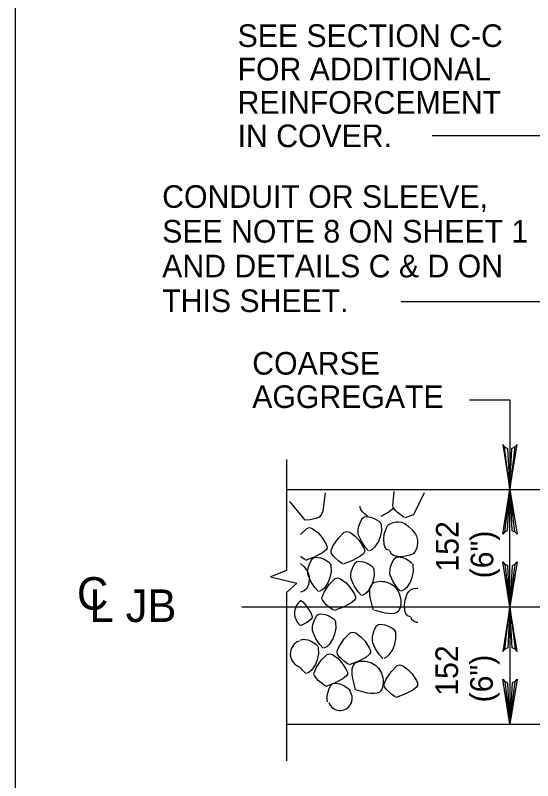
# Model space of a CAD drawing. Extents: x 638455 to 640199, y 298558 to 299152.
# Drawn here: x 639333.6 to 639410.6, y 298979.8 to 299093.5 of the extents above; entities that cross this region are included whole.
import ezdxf

# ---------------------------------------------------------------- set-up
doc = ezdxf.new("R2010")
doc.units = 0
for name, color, linetype in [('1', 7, 'Continuous'), ('2', 7, 'Continuous'), ('3', 7, 'Continuous')]:
    doc.layers.add(name, color=color, linetype=linetype)

msp = doc.modelspace()

# ---------------------------------------------------------------- linework, layer by layer
at = {"layer": '1'}
msp.add_lwpolyline([(640119.61, 298573.25), (640119.61, 299137.25), (639333.61, 299137.25), (639333.61, 298573.25), (640119.61, 298573.25), (640119.61, 298599.61), (639919.61, 298599.61), (639919.61, 298664.29), (640119.61, 298664.29), (640119.61, 298693.25), (639919.61, 298693.25), (639919.61, 298573.25), (639998.42, 298573.25), (639998.42, 298599.61), (639998.42, 298573.25), (640075.42, 298573.25), (640075.42, 298599.61), (640075.42, 298587.29), (640119.61, 298587.29)], dxfattribs=at)
for centre, radius, start, end in [((639377.44, 299004.64), 2.3, 128.3504, 231.6496), ((639376.57, 298998.59), 2.06, 110.8458, 251.6988), ((639381.92, 298992), 1.8, 199.608, 34.7802)]:
    msp.add_arc(centre, radius, start, end, dxfattribs=at)
at = {"layer": '2'}
for p, q in [((639395.61, 299075.6), (639424.14, 299075.6)), ((639391.01, 299050.97), (639421.85, 299050.97)), ((639401.16, 299036.35), (639407.17, 299036.35)), ((639407.17, 299036.35), (639407.17, 299023.03)), ((639373.95, 299027.49), (639373.95, 299010.98)), ((639373.94, 299023.03), (639513.29, 299023.03)), ((639407.17, 299005.61), (639407.17, 299023.03)), ((639373.95, 299007.72), (639373.95, 298982.72)), ((639367.29, 299005.61), (639411.68, 299005.61)), ((639407.17, 299005.61), (639407.17, 298988.18)), ((639373.95, 298988.18), (639513.29, 298988.18))]:
    msp.add_line(p, q, dxfattribs=at)
for points in [[(639406.37, 299029.36), (639406.83, 299029.13), (639407.17, 299023.03), (639406.37, 299029.36), (639406.1, 299029.69), (639407.17, 299023.03), (639407.47, 299029.12), (639407.92, 299029.34), (639407.17, 299023.03), (639408.23, 299029.69), (639407.92, 299029.34)], [(639379.71, 299022.54), (639379.33, 299019.82)], [(639389.76, 299020.61), (639389.94, 299022.71)], [(639394.41, 299022.54), (639392.83, 299019.27)], [(639406.37, 299016.7), (639406.83, 299016.94), (639407.17, 299023.03), (639406.37, 299016.7), (639406.1, 299016.38), (639407.17, 299023.03), (639407.47, 299016.94), (639407.92, 299016.72), (639407.17, 299023.03), (639408.23, 299016.38), (639407.92, 299016.72)], [(639376.71, 299018.49), (639374.46, 299021.25)], [(639384.9, 299020.36), (639384.91, 299020.57)], [(639384.96, 299020.14), (639384.9, 299020.36)], [(639385.25, 299019.71), (639384.96, 299020.14)], [(639389.72, 299020.1), (639389.18, 299019.66)], [(639389.87, 299020.35), (639389.72, 299020.1)], [(639389.82, 299020.39), (639389.76, 299020.61)], [(639390.11, 299019.96), (639389.82, 299020.39)], [(639390.39, 299019.67), (639390.11, 299019.96)], [(639378.36, 299018.72), (639377.44, 299018.5)], [(639378.78, 299018.93), (639378.36, 299018.72)], [(639379.1, 299019.25), (639378.78, 299018.93)], [(639379.33, 299019.82), (639379.1, 299019.25)], [(639384.93, 299018.22), (639385.23, 299018.77)], [(639385.23, 299018.77), (639385.48, 299018.97)], [(639385.54, 299019.42), (639385.25, 299019.71)], [(639385.48, 299018.97), (639385.79, 299019.03)], [(639385.98, 299019.06), (639385.54, 299019.42)], [(639385.79, 299019.03), (639386.46, 299018.93)], [(639386.46, 299018.93), (639386.99, 299018.73)], [(639386.99, 299018.73), (639387.67, 299018.31)], [(639389.18, 299019.66), (639387.97, 299019.02)], [(639390.84, 299019.3), (639390.39, 299019.67)], [(639391.46, 299018.85), (639390.84, 299019.3)], [(639392.83, 299019.27), (639391.54, 299018.79)], [(639377.44, 299018.5), (639376.71, 299018.49)], [(639384.6, 299017.11), (639384.7, 299017.57)], [(639384.7, 299017.57), (639384.93, 299018.22)], [(639387.67, 299018.31), (639387.9, 299018.07)], [(639387.9, 299018.07), (639388.02, 299017.84)], [(639388.02, 299017.84), (639388.05, 299016.86)], [(639388.8, 299017.35), (639389.03, 299017.7)], [(639389.03, 299017.7), (639389.3, 299017.93)], [(639389.3, 299017.93), (639389.8, 299018.13)], [(639389.8, 299018.13), (639390.25, 299018.21)], [(639390.25, 299018.21), (639390.6, 299018.22)], [(639390.6, 299018.22), (639391.1, 299018.15)], [(639391.1, 299018.15), (639391.55, 299017.96)], [(639391.55, 299017.96), (639392, 299017.63)], [(639392, 299017.63), (639392.61, 299017.05)], [(639376.08, 299016.37), (639376.96, 299017.25)], [(639376.96, 299017.25), (639377.35, 299017.36)], [(639377.35, 299017.36), (639377.78, 299017.23)], [(639377.78, 299017.23), (639378.58, 299016.63)], [(639378.58, 299016.63), (639379.16, 299016)], [(639381.66, 299015.81), (639382.53, 299016.69)], [(639382.53, 299016.69), (639382.93, 299016.8)], [(639382.93, 299016.8), (639383.35, 299016.66)], [(639383.35, 299016.66), (639384.16, 299016.07)], [(639384.6, 299016.53), (639384.6, 299017.11)], [(639384.67, 299016.24), (639384.6, 299016.53)], [(639388.05, 299016.86), (639387.86, 299015.97)], [(639388.49, 299016.41), (639388.8, 299017.35)], [(639392.61, 299017.05), (639393.13, 299016.38)], [(639376.04, 299016.32), (639376.08, 299016.37)], [(639379.16, 299016), (639379.8, 299015.02)], [(639380.87, 299014.68), (639381.66, 299015.81)], [(639384.16, 299016.07), (639384.73, 299015.44)], [(639385.08, 299015.33), (639384.67, 299016.24)], [(639384.73, 299015.44), (639385.38, 299014.46)], [(639385.66, 299014.45), (639385.08, 299015.33)], [(639387.61, 299015.3), (639387.04, 299014.44)], [(639387.86, 299015.97), (639387.61, 299015.3)], [(639388.41, 299015.71), (639388.49, 299016.41)], [(639388.48, 299014.84), (639388.41, 299015.71)], [(639393.13, 299016.38), (639393.27, 299016.1)], [(639393.27, 299016.1), (639393.4, 299015.51)], [(639393.4, 299015.51), (639393.41, 299015.05)], [(639379.8, 299015.02), (639379.96, 299014.61)], [(639379.97, 299014.3), (639379.82, 299014.05)], [(639379.96, 299014.61), (639379.97, 299014.3)], [(639380.59, 299013.96), (639380.87, 299014.68)], [(639385.38, 299014.46), (639385.53, 299014.05)], [(639386.16, 299013.93), (639385.66, 299014.45)], [(639387.04, 299014.44), (639386.68, 299014.13)], [(639388.62, 299014.43), (639388.48, 299014.84)], [(639388.87, 299014.09), (639388.62, 299014.43)], [(639393.3, 299014.37), (639393.07, 299013.8)], [(639393.41, 299015.05), (639393.3, 299014.37)], [(639376.09, 299013.01), (639376.04, 299013.04)], [(639379.29, 299013.61), (639378.08, 299012.98)], [(639379.82, 299014.05), (639379.29, 299013.61)], [(639380.58, 299013.75), (639380.59, 299013.96)], [(639380.64, 299013.53), (639380.58, 299013.75)], [(639380.93, 299013.1), (639380.64, 299013.53)], [(639381.21, 299012.81), (639380.93, 299013.1)], [(639384.86, 299013.05), (639383.65, 299012.41)], [(639385.4, 299013.49), (639384.86, 299013.05)], [(639385.54, 299013.74), (639385.4, 299013.49)], [(639385.53, 299014.05), (639385.54, 299013.74)], [(639386.68, 299014.13), (639386.28, 299013.93)], [(639389.3, 299013.94), (639388.87, 299014.09)], [(639389.52, 299013.49), (639389.38, 299013.88)], [(639389.86, 299013.23), (639389.52, 299013.49)], [(639390.18, 299013.11), (639389.86, 299013.23)], [(639390.68, 299013.03), (639390.18, 299013.11)], [(639391.41, 299013.05), (639390.68, 299013.03)], [(639392.34, 299013.26), (639391.41, 299013.05)], [(639392.76, 299013.48), (639392.34, 299013.26)], [(639393.07, 299013.8), (639392.76, 299013.48)], [(639376.04, 299012.03), (639376.5, 299011.59)], [(639376.7, 299012.56), (639376.09, 299013.01)], [(639378.08, 299012.98), (639376.79, 299012.5)], [(639377.23, 299011.52), (639377.46, 299012.17)], [(639377.46, 299012.17), (639377.76, 299012.72)], [(639377.76, 299012.72), (639378.01, 299012.92)], [(639378.01, 299012.92), (639378.32, 299012.98)], [(639378.32, 299012.98), (639378.99, 299012.88)], [(639378.99, 299012.88), (639379.52, 299012.68)], [(639379.52, 299012.68), (639380.2, 299012.26)], [(639380.2, 299012.26), (639380.43, 299012.02)], [(639380.43, 299012.02), (639380.55, 299011.79)], [(639381.66, 299012.45), (639381.21, 299012.81)], [(639382.28, 299011.99), (639381.66, 299012.45)], [(639383.65, 299012.41), (639382.36, 299011.93)], [(639383.86, 299011.59), (639384.16, 299012.14)], [(639384.16, 299012.14), (639384.41, 299012.34)], [(639384.41, 299012.34), (639384.72, 299012.4)], [(639384.72, 299012.4), (639385.39, 299012.3)], [(639385.39, 299012.3), (639385.92, 299012.1)], [(639385.92, 299012.1), (639386.6, 299011.68)], [(639389.43, 299011.54), (639389.67, 299012.19)], [(639389.67, 299012.19), (639389.97, 299012.74)], [(639389.97, 299012.74), (639390.21, 299012.94)], [(639390.21, 299012.94), (639390.52, 299013)], [(639390.52, 299013), (639391.19, 299012.9)], [(639391.19, 299012.9), (639391.72, 299012.7)], [(639391.72, 299012.7), (639392.4, 299012.28)], [(639392.4, 299012.28), (639392.63, 299012.04)], [(639392.63, 299012.04), (639392.75, 299011.81)], [(639407.96, 299011.94), (639407.5, 299011.7), (639407.17, 299005.61), (639407.96, 299011.94), (639408.24, 299012.26), (639407.17, 299005.61), (639406.87, 299011.69), (639406.41, 299011.92), (639407.17, 299005.61), (639406.11, 299012.26), (639406.41, 299011.92)], [(639373.95, 299010.98), (639371.57, 299010.07), (639375.5, 299009.1), (639373.95, 299007.72)], [(639376.5, 299011.59), (639377.01, 299010.93)], [(639377.01, 299010.93), (639377.16, 299010.64)], [(639377.13, 299011.06), (639377.23, 299011.52)], [(639377.13, 299010.49), (639377.13, 299011.06)], [(639380.58, 299010.81), (639380.39, 299009.92)], [(639380.55, 299011.79), (639380.58, 299010.81)], [(639383.53, 299010.49), (639383.63, 299010.94)], [(639383.63, 299010.94), (639383.86, 299011.59)], [(639386.6, 299011.68), (639386.83, 299011.45)], [(639386.83, 299011.45), (639386.95, 299011.21)], [(639386.95, 299011.21), (639386.98, 299010.24)], [(639389.33, 299010.51), (639389.34, 299011.08)], [(639389.34, 299011.08), (639389.43, 299011.54)], [(639392.78, 299010.83), (639392.59, 299009.94)], [(639392.75, 299011.81), (639392.78, 299010.83)], [(639377.2, 299010.19), (639377.13, 299010.49)], [(639377.16, 299010.64), (639377.29, 299010.06)], [(639377.61, 299009.28), (639377.2, 299010.19)], [(639377.29, 299010.06), (639377.3, 299009.59)], [(639380.39, 299009.92), (639380.14, 299009.25)], [(639380.3, 299008.9), (639381.18, 299009.78)], [(639381.18, 299009.78), (639381.57, 299009.89)], [(639381.57, 299009.89), (639381.99, 299009.75)], [(639381.99, 299009.75), (639382.8, 299009.16)], [(639383.53, 299009.91), (639383.53, 299010.49)], [(639383.6, 299009.61), (639383.53, 299009.91)], [(639384.01, 299008.7), (639383.6, 299009.61)], [(639386.98, 299010.24), (639386.79, 299009.34)], [(639389.4, 299010.21), (639389.33, 299010.51)], [(639389.81, 299009.3), (639389.4, 299010.21)], [(639392.59, 299009.94), (639392.34, 299009.27)], [(639377.19, 299008.91), (639376.96, 299008.34)], [(639377.3, 299009.59), (639377.19, 299008.91)], [(639378.19, 299008.4), (639377.61, 299009.28)], [(639379.52, 299007.76), (639380.3, 299008.9)], [(639380.14, 299009.25), (639379.58, 299008.39)], [(639382.8, 299009.16), (639383.38, 299008.53)], [(639383.38, 299008.53), (639384.02, 299007.55)], [(639384.59, 299007.83), (639384.01, 299008.7)], [(639386.54, 299008.68), (639385.97, 299007.82)], [(639386.79, 299009.34), (639386.54, 299008.68)], [(639390.39, 299008.42), (639389.81, 299009.3)], [(639392.34, 299009.27), (639391.78, 299008.42)], [(639376.22, 299007.81), (639376.04, 299007.77)], [(639376.64, 299008.03), (639376.22, 299007.81)], [(639376.96, 299008.34), (639376.64, 299008.03)], [(639378.69, 299007.88), (639378.19, 299008.4)], [(639379.22, 299008.08), (639378.81, 299007.88)], [(639379.58, 299008.39), (639379.22, 299008.08)], [(639379.23, 299007.05), (639379.52, 299007.76)], [(639384.02, 299007.55), (639384.18, 299007.13)], [(639385.09, 299007.3), (639384.59, 299007.83)], [(639385.62, 299007.51), (639385.2, 299007.3)], [(639385.97, 299007.82), (639385.62, 299007.51)], [(639390.9, 299007.9), (639390.39, 299008.42)], [(639391.42, 299008.1), (639391.01, 299007.9)], [(639391.78, 299008.42), (639391.42, 299008.1)], [(639391.57, 299006.58), (639391.88, 299007.51)], [(639391.88, 299007.51), (639392.11, 299007.87)], [(639392.11, 299007.87), (639392.38, 299008.1)], [(639392.38, 299008.1), (639392.89, 299008.3)], [(639392.89, 299008.3), (639393.34, 299008.37)], [(639393.34, 299008.37), (639393.47, 299008.38)], [(639376.04, 299006.56), (639376.35, 299006.33)], [(639376.35, 299006.33), (639376.93, 299005.7)], [(639379.22, 299006.84), (639379.23, 299007.05)], [(639379.29, 299006.62), (639379.22, 299006.84)], [(639379.57, 299006.19), (639379.29, 299006.62)], [(639384.04, 299006.58), (639383.5, 299006.14)], [(639384.19, 299006.83), (639384.04, 299006.58)], [(639384.18, 299007.13), (639384.19, 299006.83)], [(639391.5, 299005.88), (639391.57, 299006.58)], [(639376.93, 299005.7), (639377.57, 299004.72)], [(639379.86, 299005.91), (639379.57, 299006.19)], [(639380.3, 299005.54), (639379.86, 299005.91)], [(639380.92, 299005.08), (639380.3, 299005.54)], [(639382.29, 299005.51), (639381.01, 299005.03)], [(639383.5, 299006.14), (639382.29, 299005.51)], [(639391.56, 299005), (639391.5, 299005.88)], [(639407.96, 298999.28), (639407.5, 298999.51), (639407.17, 299005.61), (639407.96, 298999.28), (639408.24, 298998.95), (639407.17, 299005.61), (639406.87, 298999.52), (639406.41, 298999.3), (639407.17, 299005.61), (639406.11, 298998.95), (639406.41, 298999.3)], [(639377.57, 299004.72), (639377.73, 299004.31)], [(639377.74, 299004), (639377.59, 299003.75)], [(639377.73, 299004.31), (639377.74, 299004)], [(639378.16, 299003.75), (639378.46, 299004.3)], [(639378.46, 299004.3), (639378.71, 299004.5)], [(639378.71, 299004.5), (639379.02, 299004.56)], [(639379.02, 299004.56), (639379.69, 299004.46)], [(639379.69, 299004.46), (639380.22, 299004.26)], [(639380.22, 299004.26), (639380.9, 299003.84)], [(639391.7, 299004.59), (639391.56, 299005)], [(639391.96, 299004.25), (639391.7, 299004.59)], [(639392.38, 299004.1), (639391.96, 299004.25)], [(639392.6, 299003.66), (639392.47, 299004.04)], [(639377.05, 299003.31), (639376.04, 299002.78)], [(639377.59, 299003.75), (639377.05, 299003.31)], [(639377.83, 299002.65), (639377.93, 299003.1)], [(639377.93, 299003.1), (639378.16, 299003.75)], [(639380.9, 299003.84), (639381.13, 299003.61)], [(639381.13, 299003.61), (639381.25, 299003.38)], [(639381.25, 299003.38), (639381.28, 299002.4)], [(639387.35, 299002.78), (639387.6, 299002.98)], [(639387.6, 299002.98), (639387.91, 299003.04)], [(639387.91, 299003.04), (639388.58, 299002.94)], [(639388.58, 299002.94), (639389.11, 299002.74)], [(639392.95, 299003.39), (639392.6, 299003.66)], [(639393.27, 299003.28), (639392.95, 299003.39)], [(639393.47, 299003.25), (639393.27, 299003.28)], [(639377.83, 299002.07), (639377.83, 299002.65)], [(639377.9, 299001.77), (639377.83, 299002.07)], [(639378.31, 299000.86), (639377.9, 299001.77)], [(639381.28, 299002.4), (639381.09, 299001.51)], [(639382.54, 299000.86), (639383.42, 299001.74)], [(639383.42, 299001.74), (639383.82, 299001.84)], [(639383.82, 299001.84), (639384.24, 299001.71)], [(639384.24, 299001.71), (639385.04, 299001.11)], [(639386.82, 299001.58), (639387.05, 299002.23)], [(639387.05, 299002.23), (639387.35, 299002.78)], [(639389.11, 299002.74), (639389.79, 299002.32)], [(639389.79, 299002.32), (639390.02, 299002.08)], [(639390.02, 299002.08), (639390.14, 299001.85)], [(639390.14, 299001.85), (639390.17, 299000.88)], [(639376.04, 299000.66), (639376.12, 299000.71)], [(639376.12, 299000.71), (639376.43, 299000.77)], [(639376.43, 299000.77), (639377.1, 299000.68)], [(639377.1, 299000.68), (639377.63, 299000.48)], [(639378.89, 298999.99), (639378.31, 299000.86)], [(639380.84, 299000.84), (639380.28, 298999.98)], [(639381.09, 299001.51), (639380.84, 299000.84)], [(639381.76, 298999.72), (639382.54, 299000.86)], [(639385.04, 299001.11), (639385.62, 299000.48)], [(639386.72, 299001.12), (639386.82, 299001.58)], [(639386.72, 299000.55), (639386.72, 299001.12)], [(639386.79, 299000.25), (639386.72, 299000.55)], [(639390.17, 299000.88), (639389.98, 298999.98)], [(639377.63, 299000.48), (639378.31, 299000.05)], [(639378.31, 299000.05), (639378.54, 298999.82)], [(639378.54, 298999.82), (639378.66, 298999.59)], [(639378.66, 298999.59), (639378.69, 298998.61)], [(639379.39, 298999.46), (639378.89, 298999.99)], [(639379.92, 298999.67), (639379.51, 298999.46)], [(639380.28, 298999.98), (639379.92, 298999.67)], [(639381.48, 298999.01), (639381.76, 298999.72)], [(639385.62, 299000.48), (639386.26, 298999.5)], [(639386.26, 298999.5), (639386.42, 298999.09)], [(639387.2, 298999.34), (639386.79, 299000.25)], [(639389.98, 298999.98), (639389.73, 298999.31)], [(639378.69, 298998.61), (639378.5, 298997.72)], [(639379.11, 298997.65), (639379.98, 298998.53)], [(639379.98, 298998.53), (639380.38, 298998.63)], [(639380.38, 298998.63), (639380.8, 298998.5)], [(639380.8, 298998.5), (639381.61, 298997.9)], [(639381.47, 298998.79), (639381.48, 298999.01)], [(639381.53, 298998.58), (639381.47, 298998.79)], [(639381.82, 298998.14), (639381.53, 298998.58)], [(639386.28, 298998.54), (639385.75, 298998.09)], [(639386.43, 298998.78), (639386.28, 298998.54)], [(639386.42, 298999.09), (639386.43, 298998.78)], [(639387.78, 298998.46), (639387.2, 298999.34)], [(639388.28, 298997.94), (639387.78, 298998.46)], [(639389.16, 298998.45), (639388.8, 298998.14)], [(639389.73, 298999.31), (639389.16, 298998.45)], [(639378.5, 298997.72), (639378.24, 298997.05)], [(639378.33, 298996.51), (639379.11, 298997.65)], [(639381.61, 298997.9), (639382.18, 298997.27)], [(639382.1, 298997.86), (639381.82, 298998.14)], [(639382.55, 298997.49), (639382.1, 298997.86)], [(639382.18, 298997.27), (639382.83, 298996.29)], [(639383.17, 298997.04), (639382.55, 298997.49)], [(639384.54, 298997.46), (639383.25, 298996.98)], [(639385.75, 298998.09), (639384.54, 298997.46)], [(639388.8, 298998.14), (639388.4, 298997.94)], [(639376.3, 298996.2), (639376.04, 298996.58)], [(639376.8, 298995.68), (639376.3, 298996.2)], [(639377.68, 298996.19), (639377.32, 298995.88)], [(639378.24, 298997.05), (639377.68, 298996.19)], [(639378.04, 298995.8), (639378.33, 298996.51)], [(639382.83, 298996.29), (639382.99, 298995.88)], [(639388.76, 298994.86), (639389.54, 298996)], [(639389.54, 298996), (639390.42, 298996.88)], [(639390.42, 298996.88), (639390.81, 298996.98)], [(639390.81, 298996.98), (639391.24, 298996.85)], [(639391.24, 298996.85), (639392.04, 298996.25)], [(639392.04, 298996.25), (639392.62, 298995.63)], [(639377.32, 298995.88), (639376.91, 298995.68)], [(639378.03, 298995.59), (639378.04, 298995.8)], [(639378.09, 298995.37), (639378.03, 298995.59)], [(639378.38, 298994.93), (639378.09, 298995.37)], [(639378.66, 298994.65), (639378.38, 298994.93)], [(639382.31, 298994.88), (639381.1, 298994.25)], [(639382.85, 298995.33), (639382.31, 298994.88)], [(639382.99, 298995.57), (639382.85, 298995.33)], [(639382.99, 298995.88), (639382.99, 298995.57)], [(639388.47, 298994.15), (639388.76, 298994.86)], [(639392.62, 298995.63), (639393.26, 298994.65)], [(639407.96, 298994.51), (639407.5, 298994.28), (639407.17, 298988.18), (639407.96, 298994.51), (639408.24, 298994.84), (639407.17, 298988.18), (639406.87, 298994.27), (639406.41, 298994.49), (639407.17, 298988.18), (639406.11, 298994.84), (639406.41, 298994.49)], [(639379.11, 298994.28), (639378.66, 298994.65)], [(639379.73, 298993.83), (639379.11, 298994.28)], [(639381.1, 298994.25), (639379.81, 298993.77)], [(639380.3, 298993.44), (639380.6, 298993.99)], [(639380.6, 298993.99), (639380.85, 298994.19)], [(639380.85, 298994.19), (639381.16, 298994.25)], [(639381.16, 298994.25), (639381.83, 298994.15)], [(639381.83, 298994.15), (639382.36, 298993.95)], [(639382.36, 298993.95), (639383.04, 298993.53)], [(639388.46, 298993.94), (639388.47, 298994.15)], [(639388.52, 298993.72), (639388.46, 298993.94)], [(639388.81, 298993.29), (639388.52, 298993.72)], [(639393.26, 298994.65), (639393.42, 298994.23)], [(639393.43, 298993.92), (639393.28, 298993.68)], [(639393.42, 298994.23), (639393.43, 298993.92)], [(639379.97, 298992.34), (639380.07, 298992.79)], [(639380.07, 298992.79), (639380.3, 298993.44)], [(639383.04, 298993.53), (639383.27, 298993.3)], [(639383.27, 298993.3), (639383.39, 298993.06)], [(639389.1, 298993), (639388.81, 298993.29)], [(639389.54, 298992.63), (639389.1, 298993)], [(639390.16, 298992.18), (639389.54, 298992.63)], [(639391.53, 298992.6), (639390.25, 298992.12)], [(639392.74, 298993.23), (639391.53, 298992.6)], [(639393.28, 298993.68), (639392.74, 298993.23)], [(639379.97, 298991.76), (639379.97, 298992.34)], [(639380.04, 298991.46), (639379.97, 298991.76)]]:
    msp.add_lwpolyline(points, dxfattribs=at)
for points in [[(639386.86, 299005.14), (639386.86, 299009.14), (639389.11, 299009.17), (639390.68, 299007.59), (639390.63, 299005), (639386.94, 299005.09)], [(639384.22, 298993.27), (639384.22, 298997.27), (639386.48, 298997.3), (639388.05, 298995.72), (639387.99, 298993.13), (639384.31, 298993.22)]]:
    msp.add_spline(points, degree=3, dxfattribs=at)

# ---------------------------------------------------------------- texts
at = {"layer": '3'}
for s, height, p in [('SEE SECTION C-C', 3.36, (639366.67, 299088.76)), ('FOR ADDITIONAL', 3.36, (639366.67, 299083.8)), ('REINFORCEMENT', 3.36, (639366.67, 299078.84)), ('IN COVER.', 3.36, (639366.67, 299073.88)), ('CONDUIT OR SLEEVE,', 3.36, (639355.46, 299064.86)), ('SEE NOTE 8 ON SHEET 1', 3.36, (639355.46, 299059.7)), ('AND DETAILS C & D ON', 3.36, (639355.46, 299054.54)), ('THIS SHEET.', 3.36, (639355.46, 299049.38)), ('COARSE', 3.36, (639368.85, 299040.09)), ('AGGREGATE', 3.36, (639368.85, 299035.13)), ('C', 4.84, (639342.78, 299005.16)), ('L JB', 4.838, (639344.64, 299003.34))]:
    msp.add_text(s, height=height, dxfattribs=at).set_placement(p)
for s, p in [('152', (639399.53, 299010.82)), ('(6")', (639404.69, 299009.82)), ('152', (639399.45, 298992.38)), ('(6")', (639404.61, 298991.39))]:
    msp.add_text(s, height=3.36, rotation=90, dxfattribs=at).set_placement(p)

doc.saveas('drawing.dxf')
